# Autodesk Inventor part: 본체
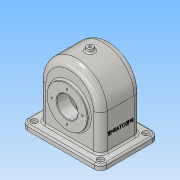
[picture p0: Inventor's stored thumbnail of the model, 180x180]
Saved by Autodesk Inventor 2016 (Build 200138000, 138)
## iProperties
Created: 2018-08
Part Number: 본체
Material: 알루미늄 6061
Document SubType Name: Modeling
Designer: Administrator
Density: 2.7 g/cm^3
Appearance: 알루미늄 - 평지
Mass: 1091.9 g
Surface Area: 1182.65 cm^2
Volume: 404.407 cm^3
Author: Administrator
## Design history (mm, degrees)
sketch "스케치1"
  geometry: L1 (-75, -55)-(75, -55); L2 (75, -55)-(75, 55); L3 (75, 55)-(-75, 55); L4 (-75, 55)-(-75, -55); L5 (-75, -55)-(75, 55); L6 (75, -55)-(-75, 55); 1 further point
  constraints: 12 end point, 2 midpoint, 2 parallel, 1 horizontal, 1 perpendicular
  dimensions: "d0" = 150 distance of L3.end L2.end; "d1" = 110 distance of L2.end L1.end
extrude "돌출1" new body sketch "스케치1" distance "d2" = 10; taper "d3" = 0 deg
sketch "스케치2"
  geometry: L1 (0, 0)-(0, 78); L2 (58, 78)-(58, 0); L3 (-75, 0)-(75, 0) reference; L4 (-58, 78)-(-58, 0); L5 (0, 78)-(58, 78); L6 (58, 0)-(-58, 0); A1 r 58 centre (0, 78) between (-58, 78) and (58, 78); A2 r 58 centre (0, 78) between (58, 78) and (-58, 78)
  constraints: 10 end point, 4 point on circle, 2 centre point, 2 point on line, 2 vertical, 1 coincident, 1 collinear, 1 horizontal, 1 perpendicular, 1 tangent
  dimensions: "d4" = 78 distance of L1.start L1.end; "d5" = 116 diameter of A1
extrude "돌출2" join sketch "스케치2" stored distance "d6" = 77; taper "d7" = 0 deg
feature "쉘1" dims "d8" = 10, "d9" = 6, "d10" = 5
sketch "스케치3"
  geometry: L1 (0, 0)-(0, 65); C1 r 38 at (0, 65)
  constraints: 2 end point, 1 centre point, 1 coincident, 1 vertical
  dimensions: "d11" = 65 distance of L1.start L1.end; "d12" = 76 diameter of C1
extrude "돌출3" join sketch "스케치3" distance "d13" = 5; taper "d14" = 0 deg
sketch "스케치4"
  geometry: L1 (0, 0)-(0, -65); C1 r 38 at (0, -65)
  constraints: 2 end point, 1 centre point, 1 coincident, 1 vertical
  dimensions: "d16" = 65 distance of L1.start L1.end; "d17" = 76 diameter of C1
extrude "돌출4" join sketch "스케치4" distance "d18" = 10; taper "d19" = 0 deg
sketch "스케치5"
  geometry: L1 (-43.5, 103)-(-43.5, 27) reference; L2 (-43.5, 65)-(48.5, 65); L3 (48.5, 27)-(48.5, 103) reference; L4 (-19.5, 65)-(-19.5, 93); L5 (-19.5, 93)-(-33.5, 104.747); L6 (-33.5, 130)-(-33.5, 78) reference; L7 (0, 0)-(0, 136); L8 (-38.5, 136)-(38.5, 136) reference; L9 (-33.5, 104.747)-(-33.5, 65); L10 (-33.5, 78)-(-33.5, 0) reference
  constraints: 10 end point, 4 point on line, 3 midpoint, 1 vertical
  dimensions: "d21" = 56 diameter of L4.end L2; "d22" = 50 deg angle of L5 L4; "d24" = 24 distance between parallel lines of L1 L4
revolve "회전1" sketch "스케치5" stored, may be unused: angle "d25" = 90 deg
hole "구멍1" diameter "d28" = 40; stored, may be unused: countersink angle "d32" = 90 deg, drill point angle "d34" = 118 deg; dims "d26" = 10, "d27" = 10, "d29" = 6, "d30" = 4, "d31" = 2, "d33" = 8
sketch "스케치6" dims "d35" = 58
  geometry: L1 (0, 0)-(0, 29); C1 r 38 at (0, 0) reference; C2 r 38 at (0, 0) reference; 2 further points
  constraints: 2 end point, 1 coincident, 1 vertical, 1 vertical alignment, 2 other
hole "구멍2" sketch "스케치6" at (0, 29) diameter "d36" = 3.242; stored, may be unused: countersink angle "d40" = 90 deg, drill point angle "d42" = 118 deg; dims "d37" = 8, "d38" = 4, "d39" = 2, "d41" = 10
sketch "스케치7"
  geometry: L1 (0, 0)-(0, -29); C1 r 38 at (0, 0) reference; C2 r 29 at (0, 0); C3 r 1.621 at (0, -29) reference; 1 further point
  constraints: 2 end point, 1 centre point, 1 coincident, 1 vertical
  dimensions: "d46" = 58 diameter of C2
hole "구멍3" sketch "스케치7" at (0, -29) diameter "d47" = 3.242; stored, may be unused: countersink angle "d51" = 90 deg, drill point angle "d53" = 118 deg; dims "d48" = 8, "d49" = 4, "d50" = 2, "d52" = 10
fillet "모깎기1" dims "d57" = 12
fillet "모깎기2" dims "d58" = 13
fillet "모깎기3" dims "d59" = 3
node "작업 평면1"
sketch "스케치8"
  geometry: L1 (-58, 25.5)-(58, 25.5) reference; L2 (-58, 25.5)-(-58, -25.5) reference; L3 (58, -25.5)-(-58, -25.5) reference; L4 (58, -25.5)-(58, 25.5) reference; L5 (-75, 43)-(-75, -43) reference; L6 (-75, 0)-(75, 0); L7 (75, -43)-(75, 43) reference; L8 (63, 55)-(-63, 55) reference; L9 (0, 55)-(0, -55); L10 (-63, -55)-(63, -55) reference; C1 r 6 at (0, 0); 1 further point
  constraints: 4 end point, 4 midpoint, 1 centre point, 1 coincident
  dimensions: "d61" = 12 diameter of C1
extrude "돌출5" join sketch "스케치8" stored distance "d62" = 10; taper "d63" = 5 deg
hole "구멍4" diameter "d66" = 4.459; stored, may be unused: countersink angle "d70" = 90 deg, drill point angle "d72" = 118 deg; dims "d64" = 10, "d65" = 10, "d67" = 10, "d68" = 4, "d69" = 2, "d71" = 12.8
hole "구멍5" diameter "d75" = 5; stored, may be unused: countersink angle "d79" = 90 deg, drill point angle "d81" = 118 deg; dims "d73" = 10, "d74" = 10, "d76" = 10, "d77" = 12, "d78" = 4, "d80" = 12.8
fillet "모깎기4" dims "d82" = 3
fillet "모깎기5" dims "d83" = 3
fillet "모깎기6" dims "d84" = 8
chamfer "모따기1" distance "d85" = 1; stored, may be unused: second distance "d86" = 2, angle "d87" = 45 deg
sketch "스케치9"
  geometry: L1 (78, -17.5)-(78, 68.5) reference; L2 (0, -13)-(65, -13) reference; 2 further points
  constraints: 1 other
  dimensions: "d88" = 40 distance from line of L1 point (38, 25.5); "d89" = 38.5 distance from line of point (38, 25.5) L2
feature "엠보싱1" sketch "스케치9" dims "d0" = 150, "d1" = 110, "d90" = 0.5, "d91" = 0
sketch "스케치10"
  geometry: L1 (-80.034, 150.864)-(68.801, 150.864); L2 (68.801, 150.864)-(68.801, -15.133); L3 (68.801, -15.133)-(-80.034, -15.133); L4 (-80.034, -15.133)-(-80.034, 150.864); 1 further point
  constraints: 8 end point, 2 parallel, 1 horizontal, 1 perpendicular
extrude "돌출6" cut sketch "스케치10" stored distance "d92" = 10; taper "d93" = 0 deg
node "솔리드1"
pattern_circular "원형 패턴1" dims angle "d44" = 360 deg
pattern_circular "원형 패턴2" dims angle "d55" = 360 deg
mirror "대칭1"
mirror "대칭2"
node "투영된 루프1"
other parameters: "d60" = 142
